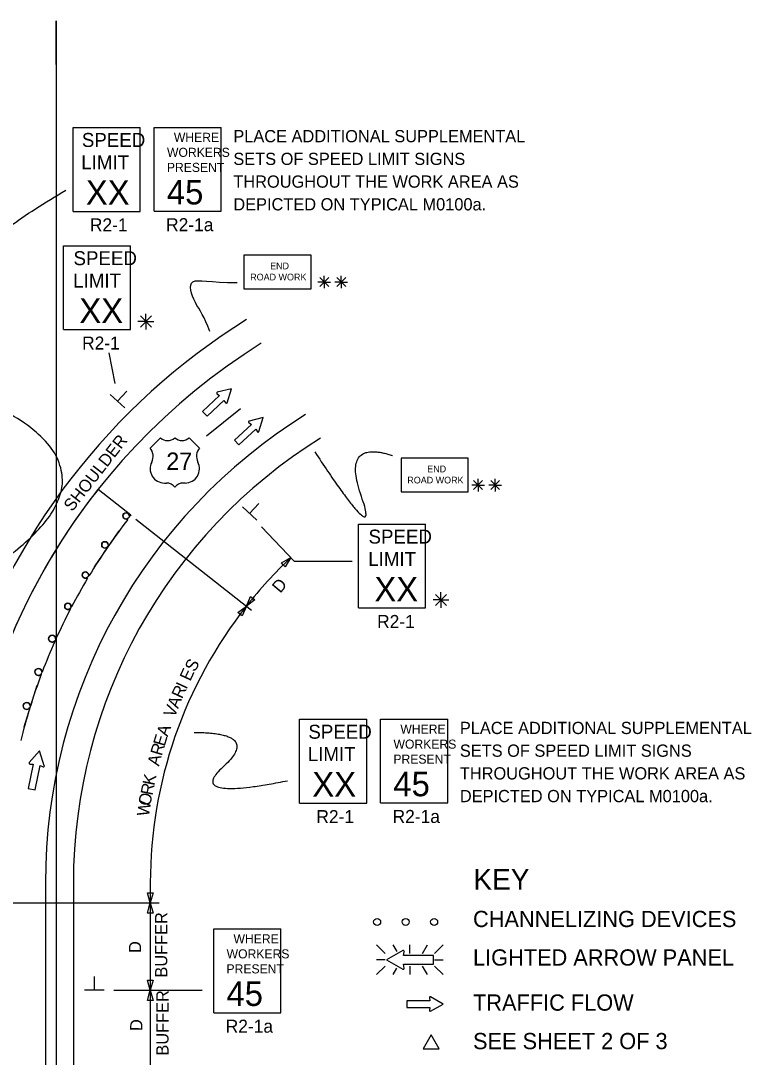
# Model space of a CAD drawing. Extents: x 16512 to 19504, y 5761 to 6984.
# Drawn here: x 16984 to 17402, y 6391 to 6984 of the extents above; entities that cross this region are included whole.
import ezdxf

# ---------------------------------------------------------------- set-up
doc = ezdxf.new("R2010")
doc.units = 0
for name, color, linetype in [('ALI_LEGAL_EX', 7, 'Continuous'), ('MT_SCRATCH_LEVEL_A', 7, 'Continuous'), ('MT_SCRATCH_LEVEL_E', 7, 'Continuous'), ('PAVT_EDGE_EX', 7, 'Continuous'), ('TRAFFIC_SIGNS_PR', 7, 'Continuous'), ('TYPICAL_EX', 7, 'Continuous'), ('TYPICAL_TEXT_DIMEN_EX', 7, 'Continuous'), ('TYPICAL_TEXT_DIMEN_PR', 7, 'Continuous')]:
    doc.layers.add(name, color=color, linetype=linetype)

msp = doc.modelspace()

# ---------------------------------------------------------------- linework, layer by layer
at = {"layer": 'ALI_LEGAL_EX'}
for p, q in [((17004.68, 6984.25), (17004.68, 6166.11)), ((17004.68, 6932.34), (17004.68, 6068.43))]:
    msp.add_line(p, q, dxfattribs=at)
for points in [[(17004.68, 6959.25), (17004.68, 6984.25)], [(17090.52, 6746.61), (17109.97, 6762.31)], [(17026.51, 6671.6), (17040.64, 6692.23)], [(16986.38, 6579.95), (16993.83, 6603.82)]]:
    msp.add_lwpolyline(points, dxfattribs=at)
at = {"layer": 'MT_SCRATCH_LEVEL_A'}
for points in [[(17047.4, 6701.11), (17028.55, 6715.96)], [(17046.41, 6700.9), (17047.26, 6700.92)], [(17045.52, 6698.69), (17045.06, 6699.05)], [(17033.55, 6682.22), (17033.12, 6682.51)], [(17034.27, 6684.19), (17034.69, 6683.89)], [(17022.59, 6665.07), (17022.2, 6665.3)], [(17023.15, 6666.89), (17023.54, 6666.65)], [(17012.67, 6647.29), (17012.32, 6647.48)], [(17013.08, 6648.95), (17013.44, 6648.76)], [(17003.81, 6628.89), (17003.65, 6628.96)], [(17004.31, 6630.44), (17004.48, 6630.37)], [(16996.47, 6611.43), (16996.6, 6611.38)], [(16996.1, 6610.07), (16995.98, 6610.11)], [(16989.53, 6590.82), (16989.45, 6590.85)], [(16989.79, 6591.97), (16989.88, 6591.95)]]:
    msp.add_lwpolyline(points, dxfattribs=at)
for centre, radius, start, end in [((17314.45, 6490.66), 364, 141.75977, 180), ((17044.61, 6700.79), 1.8, 3.5129, 180), ((17044.61, 6700.79), 1.8, 180, 284.5518), ((17314.45, 6490.66), 340, 141.75977, 141.79923), ((17314.45, 6490.66), 340, 142.2759, 145.36613), ((17314.45, 6490.66), 340, 145.70741, 148.82754), ((17032.47, 6684.19), 1.8, 0, 180), ((17032.47, 6684.19), 1.8, 180, 291.41483), ((17314.45, 6490.66), 340, 149.13833, 152.28953), ((17021.35, 6666.89), 1.8, 0, 180), ((17021.35, 6666.89), 1.8, 180, 298.27665), ((17314.45, 6490.66), 340, 152.56868, 155.7382), ((17011.28, 6648.95), 1.8, 0, 180), ((17011.28, 6648.95), 1.8, 180, 305.13736), ((17314.45, 6490.66), 340, 156.0121, 159.20322), ((17002.31, 6630.44), 2, 0, 180), ((17002.31, 6630.44), 2, 180, 312.02419), ((16994.47, 6611.43), 2, 0, 180), ((16994.47, 6611.43), 2, 180, 318.87971), ((17314.45, 6490.66), 340, 159.43985, 162.66867), ((16987.79, 6591.97), 2, 0, 180), ((17314.45, 6490.66), 340, 162.86719, 166.13449), ((16987.79, 6591.97), 2, 180, 325.73438)]:
    msp.add_arc(centre, radius, start, end, dxfattribs=at)
at = {"layer": 'MT_SCRATCH_LEVEL_E'}
for p, q in [((17096.59, 6770.73), (17098.04, 6769.64)), ((17104.85, 6773.5), (17096.76, 6771.54)), ((17102.41, 6765.52), (17104.85, 6773.5)), ((17098.04, 6769.64), (17088.37, 6760.58)), ((17090.92, 6757.85), (17100.6, 6766.91)), ((17100.6, 6766.91), (17101.58, 6765.4)), ((17088.37, 6760.58), (17090.92, 6757.85)), ((17116.24, 6753.17), (17106.57, 6744.11)), ((17114.79, 6754.26), (17116.24, 6753.17)), ((17123.06, 6757.03), (17114.96, 6755.07)), ((17120.61, 6749.05), (17123.06, 6757.03)), ((17109.13, 6741.38), (17118.8, 6750.44)), ((17118.8, 6750.44), (17119.78, 6748.93)), ((17106.57, 6744.11), (17109.13, 6741.38)), ((17218.4, 6423.17), (17205.14, 6423.17)), ((17205.14, 6423.17), (17205.14, 6419.43)), ((17218.08, 6424.95), (17218.4, 6423.17)), ((17226.01, 6421.32), (17218.77, 6425.43)), ((17218.77, 6417.17), (17226.01, 6421.32)), ((17205.14, 6419.43), (17218.4, 6419.43)), ((17218.4, 6419.43), (17218.08, 6417.65))]:
    msp.add_line(p, q, dxfattribs=at)
for centre, start, end in [((17096.87, 6771.09), 103.58205, 233.12102), ((17101.96, 6765.67), 213.1934, 342.93033), ((17115.08, 6754.62), 103.58205, 233.12102), ((17120.17, 6749.2), 213.1934, 342.93033), ((17218.54, 6425.02), 60.42484, 189.96381), ((17218.54, 6417.58), 170.03619, 299.77312)]:
    msp.add_arc(centre, 0.463, start, end, dxfattribs=at)
at = {"layer": 'PAVT_EDGE_EX'}
for p, q in [((16998.45, 6490.66), (16998.45, 6058.52)), ((17014.45, 6490.66), (17014.45, 6058.52))]:
    msp.add_line(p, q, dxfattribs=at)
for radius, start, end in [(380, 121.93275, 163.04831), (364, 121.93275, 180), (316, 121.93275, 180), (300, 121.93275, 180), (300, 180, 180.00000277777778)]:
    msp.add_arc((17314.45, 6490.66), radius, start, end, dxfattribs=at)
at = {"layer": 'TRAFFIC_SIGNS_PR'}
for p, q in [((17014.28, 6923.13), (17052.68, 6923.13)), ((17014.28, 6875.13), (17014.28, 6923.13)), ((17052.68, 6875.13), (17052.68, 6923.13)), ((17060.62, 6923.22), (17099.02, 6923.22)), ((17060.62, 6875.22), (17060.62, 6923.22)), ((17099.02, 6875.22), (17099.02, 6923.22)), ((17014.28, 6875.13), (17052.68, 6875.13)), ((17060.62, 6875.22), (17099.02, 6875.22)), ((17008.76, 6855.45), (17047.16, 6855.45)), ((17008.76, 6807.45), (17008.76, 6855.45)), ((17047.16, 6807.45), (17047.16, 6855.45)), ((17008.76, 6807.45), (17047.16, 6807.45)), ((17177.5, 6696.06), (17215.9, 6696.06)), ((17177.5, 6648.06), (17177.5, 6696.06)), ((17215.9, 6648.06), (17215.9, 6696.06)), ((17177.5, 6648.06), (17215.9, 6648.06)), ((17143.82, 6584.35), (17182.22, 6584.35)), ((17143.82, 6536.35), (17143.82, 6584.35)), ((17182.22, 6536.35), (17182.22, 6584.35)), ((17190.16, 6584.44), (17228.56, 6584.44)), ((17190.16, 6536.44), (17190.16, 6584.44)), ((17228.56, 6536.44), (17228.56, 6584.44)), ((17143.82, 6536.35), (17182.22, 6536.35)), ((17190.16, 6536.44), (17228.56, 6536.44)), ((17094.72, 6464.37), (17133.12, 6464.37)), ((17094.72, 6416.37), (17094.72, 6464.37)), ((17133.12, 6416.37), (17133.12, 6464.37)), ((17187.86, 6455.13), (17192.79, 6450.2)), ((17199.62, 6451.31), (17197.41, 6455.13)), ((17206.94, 6450.2), (17206.94, 6455.13)), ((17214.17, 6450.2), (17217.02, 6455.13)), ((17221.09, 6450.2), (17226.03, 6455.13)), ((17192.79, 6446.64), (17187.86, 6446.64)), ((17221.09, 6446.64), (17226.03, 6446.64)), ((17187.86, 6438.15), (17192.79, 6443.08)), ((17197.37, 6438.15), (17199.48, 6441.81)), ((17206.94, 6443.08), (17206.94, 6438.15)), ((17217.07, 6438.15), (17214.22, 6443.08)), ((17221.09, 6443.08), (17226.03, 6438.15)), ((17094.72, 6416.37), (17133.12, 6416.37))]:
    msp.add_line(p, q, dxfattribs=at)
for points in [[(17111.97, 6830.86), (17150.37, 6830.86), (17150.37, 6850.06), (17111.97, 6850.06)], [(17201.84, 6714.62), (17240.24, 6714.62), (17240.24, 6733.82), (17201.84, 6733.82)]]:
    msp.add_lwpolyline(points, close=True, dxfattribs=at)
for points in [[(17202.87, 6451.92), (17193.58, 6446.64), (17202.87, 6441.32)], [(17203.74, 6441.95), (17203.34, 6444.21), (17220.35, 6444.21), (17220.35, 6449.02), (17203.34, 6449.02), (17203.74, 6451.3)]]:
    msp.add_lwpolyline(points, dxfattribs=at)
for centre, radius in [((17044.61, 6700.79), 1.8), ((17032.47, 6684.19), 1.8), ((17021.35, 6666.89), 1.8), ((17011.28, 6648.95), 1.8), ((17002.31, 6630.44), 2), ((16994.47, 6611.43), 2), ((16987.79, 6591.97), 2), ((17188.2, 6468.33), 2), ((17204.5, 6468.33), 2), ((17220.8, 6468.33), 2)]:
    msp.add_circle(centre, radius, dxfattribs=at)
for centre, radius, start, end in [((17203.16, 6451.39), 0.598, 350.73078, 118.89165), ((17203.15, 6441.84), 0.597, 241.48329, 9.95933)]:
    msp.add_arc(centre, radius, start, end, dxfattribs=at)
at = {"layer": 'TYPICAL_EX'}
for p, q in [((17058.33, 6739.64), (17064.22, 6745.53)), ((17086.62, 6739.64), (17080.73, 6745.53)), ((17066.57, 6719.58), (17067.75, 6719.58)), ((17078.38, 6719.58), (17077.2, 6719.58))]:
    msp.add_line(p, q, dxfattribs=at)
for centre, radius, start, end in [((17068.35, 6749.82), 5.96, 226.14041, 313.85958), ((17076.6, 6749.83), 5.96, 226.14042, 313.85959), ((17052.74, 6734.92), 7.31, 333.09768, 40.19361), ((17092.21, 6734.92), 7.31, 139.80639, 206.90233), ((17066.59, 6727.82), 8.24, 152.6698, 269.90132), ((17078.36, 6727.82), 8.24, 270.09868, 27.3302), ((17067.77, 6713.67), 5.91, 37.1038, 90.13853), ((17077.19, 6713.67), 5.91, 89.86147, 142.8962)]:
    msp.add_arc(centre, radius, start, end, dxfattribs=at)
at = {"layer": 'TYPICAL_TEXT_DIMEN_PR'}
for p, q in [((17155.37, 6837.23), (17160.47, 6832.13)), ((17160.47, 6837.23), (17155.37, 6832.13)), ((17157.92, 6834.68), (17157.92, 6838.24)), ((17165.11, 6837.23), (17170.21, 6832.13)), ((17170.21, 6837.23), (17165.11, 6832.13)), ((17167.66, 6834.68), (17167.66, 6838.24)), ((17157.92, 6834.68), (17154.29, 6834.68)), ((17157.92, 6834.68), (17160.47, 6834.68)), ((17157.92, 6834.68), (17161.5, 6834.68)), ((17157.92, 6834.68), (17157.92, 6831.08)), ((17167.66, 6834.68), (17164.04, 6834.68)), ((17167.66, 6834.68), (17170.21, 6834.68)), ((17167.66, 6834.68), (17171.24, 6834.68)), ((17167.66, 6834.68), (17167.66, 6831.08)), ((17052.76, 6815.26), (17059.13, 6808.88)), ((17059.13, 6815.26), (17052.76, 6808.88)), ((17055.95, 6812.07), (17055.95, 6816.52)), ((17055.95, 6812.07), (17051.41, 6812.07)), ((17055.95, 6812.07), (17059.13, 6812.07)), ((17055.95, 6812.07), (17060.42, 6812.07)), ((17055.95, 6812.07), (17055.95, 6807.57)), ((17038.28, 6776.54), (17034.94, 6794.08)), ((17039.7, 6766.52), (17045, 6772.23)), ((17043.83, 6762.7), (17035.58, 6770.35)), ((17245.95, 6718.44), (17242.32, 6718.44)), ((17243.4, 6720.99), (17248.5, 6715.89)), ((17248.5, 6720.99), (17243.4, 6715.89)), ((17245.95, 6718.44), (17245.95, 6722)), ((17245.95, 6718.44), (17248.5, 6718.44)), ((17245.95, 6718.44), (17249.53, 6718.44)), ((17245.95, 6718.44), (17245.95, 6714.84)), ((17255.69, 6718.44), (17252.07, 6718.44)), ((17253.14, 6720.99), (17258.24, 6715.89)), ((17258.24, 6720.99), (17253.14, 6715.89)), ((17255.69, 6718.44), (17255.69, 6722)), ((17255.69, 6718.44), (17258.24, 6718.44)), ((17255.69, 6718.44), (17259.28, 6718.44)), ((17255.69, 6718.44), (17255.69, 6714.84)), ((17119.38, 6698.36), (17111.13, 6706.02)), ((17115.25, 6702.19), (17120.55, 6707.9)), ((17050.11, 6698.97), (17116.38, 6646.75)), ((17122.13, 6694.5), (17140.75, 6674.77)), ((17133.42, 6673.99), (17138.77, 6676.87)), ((17138.77, 6676.87), (17135.58, 6671.7)), ((17134.5, 6672.84), (17133.42, 6673.99)), ((17135.58, 6671.7), (17134.5, 6672.84)), ((17140.75, 6674.77), (17173.95, 6674.77)), ((17113.38, 6649.12), (17115.77, 6654.69)), ((17118.24, 6652.75), (17113.38, 6649.12)), ((17115.77, 6654.69), (17117.01, 6653.72)), ((17117.01, 6653.72), (17118.24, 6652.75)), ((17224.69, 6652.68), (17220.15, 6652.68)), ((17221.5, 6655.86), (17227.87, 6649.49)), ((17227.87, 6655.86), (17221.5, 6649.49)), ((17224.69, 6652.68), (17224.69, 6657.13)), ((17224.69, 6652.68), (17227.87, 6652.68)), ((17224.69, 6652.68), (17229.16, 6652.68)), ((17224.69, 6652.68), (17224.69, 6648.18)), ((17108.52, 6645.48), (17113.38, 6649.12)), ((17113.38, 6649.12), (17110.98, 6643.54)), ((17109.75, 6644.51), (17108.52, 6645.48)), ((17110.98, 6643.54), (17109.75, 6644.51)), ((17004.96, 6631.44), (17003.13, 6632.27)), ((16995.04, 6566.21), (16989.21, 6559.51)), ((16997.84, 6557.76), (16995.04, 6566.21)), ((16991.49, 6558.64), (16988.68, 6544.79)), ((16989.57, 6558.69), (16991.49, 6558.64)), ((16992.59, 6543.99), (16995.41, 6557.85)), ((16995.41, 6557.85), (16997.2, 6557.14)), ((16988.68, 6544.79), (16992.59, 6543.99)), ((17058.45, 6490.66), (17058.45, 6479.22)), ((17058.45, 6479.22), (17056.88, 6485.08)), ((17056.88, 6485.08), (17058.45, 6485.08)), ((17058.45, 6485.08), (17060.02, 6485.08)), ((17060.02, 6485.08), (17058.45, 6479.22)), ((16977.64, 6479.22), (17063.45, 6479.22)), ((17056.88, 6473.35), (17058.45, 6479.22)), ((17058.45, 6479.22), (17060.02, 6473.35)), ((17058.45, 6479.22), (17058.45, 6429.22)), ((17058.45, 6473.35), (17056.88, 6473.35)), ((17060.02, 6473.35), (17058.45, 6473.35)), ((17026.48, 6429.34), (17026.48, 6437.12)), ((17058.45, 6429.22), (17056.88, 6435.08)), ((17056.88, 6435.08), (17058.45, 6435.08)), ((17058.45, 6435.08), (17060.02, 6435.08)), ((17060.02, 6435.08), (17058.45, 6429.22)), ((17032.11, 6429.34), (17020.86, 6429.34)), ((17037.67, 6429.22), (17088.14, 6429.22)), ((17056.88, 6423.35), (17058.45, 6429.22)), ((17058.45, 6429.22), (17058.45, 6379.15)), ((17058.45, 6429.22), (17060.02, 6423.35)), ((17058.45, 6423.35), (17056.88, 6423.35)), ((17060.02, 6423.35), (17058.45, 6423.35))]:
    msp.add_line(p, q, dxfattribs=at)
msp.add_lwpolyline([(17219.07, 6403.61), (17214.55, 6395.77), (17223.6, 6395.77)], close=True, dxfattribs=at)
for centre, radius, start, end in [((17314.45, 6490.66), 256, 133.33402, 141.75968), ((17314.45, 6490.66), 256, 141.75968, 180), ((16989.59, 6559.19), 0.494, 138.95626, 268.49523), ((16997.37, 6557.61), 0.494, 248.56761, 18.30453)]:
    msp.add_arc(centre, radius, start, end, dxfattribs=at)
for points, degree in [([(16914.57, 6641.97), (17065.5, 6712.4), (16880.62, 6811.77), (17010.16, 6887.23)], 2), ([(17092.45, 6806.38), (17089.57, 6814.77), (17083.63, 6822.03), (17078.45, 6838.77), (17092.52, 6834.18), (17108.09, 6834.41)], 3), ([(17152.53, 6737.41), (17190.76, 6679.24), (17167.55, 6744.94), (17196.9, 6735.36)], 2), ([(17083.62, 6576.81), (17121.86, 6576.81), (17078.28, 6537.34), (17136.92, 6549.18)], 2)]:
    msp.add_open_spline(points, degree=degree, dxfattribs=at)

# ---------------------------------------------------------------- texts
at = {"layer": 'TRAFFIC_SIGNS_PR'}
for s, height, p in [('SPEED', 8, (17019.31, 6911.99)), ('WHERE', 5.2, (17071.93, 6914.9)), ('PLACE ADDITIONAL SUPPLEMENTAL', 7, (17105.95, 6914.67)), ('LIMIT', 8, (17018.98, 6899.19)), ('WORKERS', 5.2, (17068, 6906.3)), ('SETS OF SPEED LIMIT SIGNS', 7, (17105.95, 6901.67)), ('PRESENT', 5.2, (17067.93, 6897.7)), ('THROUGHOUT THE WORK AREA AS', 7, (17105.95, 6888.67)), ('XX', 14.031, (17021.58, 6878.89)), ('45', 14.031, (17067.92, 6879.08)), ('DEPICTED ON TYPICAL M0100a.', 7, (17105.95, 6875.67)), ('R2-1', 7.44, (17023.89, 6863.69)), ('R2-1a', 7.44, (17067.47, 6863.78)), ('SPEED', 8, (17014.53, 6844.32)), ('END', 3.831, (17126.97, 6841.98)), ('LIMIT', 8, (17014.36, 6831.52)), ('ROAD WORK', 3.831, (17115.58, 6835.6)), ('XX', 14.031, (17017.87, 6811.21)), ('R2-1', 7.44, (17019.43, 6796.01)), ('END', 3.831, (17216.84, 6725.75)), ('ROAD WORK', 3.831, (17205.45, 6719.36)), ('SPEED', 8, (17183.26, 6684.92)), ('LIMIT', 8, (17183.1, 6672.12)), ('XX', 14.031, (17186.61, 6651.82)), ('R2-1', 7.44, (17188.17, 6636.62)), ('SPEED', 8, (17148.86, 6573.21)), ('WHERE', 5.2, (17201.47, 6576.12)), ('PLACE ADDITIONAL SUPPLEMENTAL', 7, (17235.5, 6575.89)), ('WORKERS', 5.2, (17197.55, 6567.52)), ('SETS OF SPEED LIMIT SIGNS', 7, (17235.5, 6562.89)), ('LIMIT', 8, (17148.53, 6560.41)), ('PRESENT', 5.2, (17197.48, 6558.92)), ('XX', 14.031, (17151.13, 6540.11)), ('45', 14.031, (17197.47, 6540.29)), ('THROUGHOUT THE WORK AREA AS', 7, (17235.5, 6549.89)), ('DEPICTED ON TYPICAL M0100a.', 7, (17235.5, 6536.89)), ('R2-1', 7.44, (17153.43, 6524.91)), ('R2-1a', 7.44, (17197.02, 6525)), ('WHERE', 5.2, (17106.03, 6456.06)), ('WORKERS', 5.2, (17102.1, 6447.46)), ('PRESENT', 5.2, (17102.03, 6438.86)), ('45', 14.031, (17102.02, 6420.23)), ('R2-1a', 7.44, (17101.57, 6404.93))]:
    msp.add_text(s, height=height, dxfattribs=at).set_placement(p)
at = {"layer": 'TYPICAL_EX'}
msp.add_text('27', height=10, dxfattribs=at).set_placement((17067.59, 6727.06))
at = {"layer": 'TYPICAL_TEXT_DIMEN_EX'}
for s, height, p in [('KEY', 12, (17243.23, 6486.72)), ('CHANNELIZING DEVICES', 9.3, (17243.04, 6465.38)), ('LIGHTED ARROW PANEL', 9.3, (17243.04, 6443.33)), ('TRAFFIC FLOW', 9.3, (17243.04, 6417.53)), ('SEE SHEET 2 OF 3', 9.3, (17243.04, 6395.48))]:
    msp.add_text(s, height=height, dxfattribs=at).set_placement(p)
at = {"layer": 'TYPICAL_TEXT_DIMEN_PR'}
for s, rotation, p in [('SHOULDER', 52.01843, (17013.81, 6702.86)), ('D', 50, (17132.79, 6656.14)), ('S', 62.49737, (17083.98, 6611.04)), ('E', 65.17719, (17081.28, 6605.75)), ('I', 65.17719, (17079.13, 6601.09)), ('R', 65.17719, (17076.62, 6595.67)), ('V', 67.85702, (17072.25, 6584.91)), ('A', 67.85702, (17074.34, 6590.07)), ('E', 73.21667, (17066.62, 6568.45)), ('A', 70.53685, (17068.37, 6574.03)), ('R', 73.21667, (17064.99, 6563.05)), ('A', 75.8965, (17063.42, 6557.21)), ('K', 78.57633, (17060.77, 6546.08)), ('R', 78.57633, (17059.63, 6540.45)), ('O', 81.25615, (17058.54, 6534.49)), ('W', 81.25615, (17057.62, 6528.46)), ('BUFFER', 89.97949, (17068.18, 6436.48)), ('D', 89.88679, (17053.21, 6450.55)), ('BUFFER', 89.97949, (17068.89, 6391.81)), ('D', 89.88679, (17053.91, 6405.87))]:
    msp.add_text(s, height=7, rotation=rotation, dxfattribs=at).set_placement(p)

doc.saveas('drawing.dxf')
